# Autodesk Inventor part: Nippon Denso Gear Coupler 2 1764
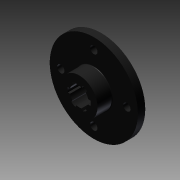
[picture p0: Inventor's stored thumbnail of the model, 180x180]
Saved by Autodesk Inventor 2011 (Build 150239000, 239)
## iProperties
Shininess: 64.0
Length Units: 11272
Angle Units: 11279
Time Units: 11290
Mass Units: 11286
Length Display Precision: 3
Angle Display Precision: 2
Category: FIRST Robotics Components
Manager: Ed Sparks
Company: FIRST CAD Library
Created: 2003-01
Part Number: Nippon Denso Gear Coupler 2 1764
Project: FIRST
Material: ABS Plastic
Document SubType Name: Modeling
Designer: Administrator
Engineer: Ed Sparks
Density: 1 g/cm^3
Density: 0.0
Volumn: 0.0
Area: 0.0
PropertySet Name: Model Information
Control State: 0
Master: False
Checked Out: False
Subject: Robot Component
Author: Administrator
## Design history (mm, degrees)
sketch "Sketch1"
  geometry: C1 r 38.1 at (0, 0)
  constraints: 1 centre point
  dimensions: "d2" = 76.2 diameter of C1
extrude "Extrusion1" new body sketch "Sketch1" stored distance "d0" = 6.35; taper "d1" = 0 deg
sketch "Sketch2"
  geometry: C1 r 38.1 at (0, 0) reference; 1 further point
  dimensions: "d3" = 0 horizontal distance of C1.centre point (0, 28.575); "d4" = 28.575 distance of C1.centre point (0, 28.575)
hole "Mounting Hole" sketch "Sketch2" at (0, 28.575) diameter "d5" = 6.35; stored, may be unused: countersink angle "d9" = 82 deg, drill point angle "d11" = 118 deg; dims "d6" = 12.7, "d7" = 9.525, "d8" = 6.35, "d10" = 19.05
pattern_circular "Circular Pattern1" dims angle "d14" = 360 deg
sketch "Sketch3"
  geometry: C1 r 38.1 at (0, 0) reference; C2 r 15.875 at (0, 0)
  constraints: 1 centre point, 1 coincident
  dimensions: "d15" = 31.75 diameter of C2
extrude "Extrusion2" join sketch "Sketch3" distance "d17" = 12.7; taper "d18" = 0 deg
sketch "Sketch8"
  geometry: C1 r 15.875 at (0, 0) reference; 1 further point
  constraints: 1 coincident
hole "Hole3" sketch "Sketch8" at (0, 0) diameter "d49" = 16.2; stored, may be unused: countersink angle "d53" = 82 deg, drill point angle "d55" = 0 deg; dims "d50" = 12.7, "d51" = 9.525, "d52" = 6.35, "d54" = 14.986
sketch "Sketch4"
  geometry: L1 (0, 0)-(-5, 8.66); L2 (0, 0)-(-10.16, 0); L3 (-2.058, 7.834)-(-3.036, 9.528); L4 (-5.556, 5.894)-(-6.528, 7.576); C1 r 15.875 at (0, 0) reference; A1 r 10 centre (0, 0) between (-3.036, 9.528) and (-6.528, 7.576); A2 r 8.1 centre (0, 0) between (-2.058, 7.834) and (-5.556, 5.894); A3 r 8.1 centre (0, 0) between (-5.556, 5.894) and (-2.058, 7.834) reference; 1 further point
  constraints: 9 end point, 7 point on circle, 2 centre point, 2 parallel, 1 coincident, 1 concentric, 1 horizontal
  dimensions: "d46" = 60 deg angle of L2 L1; "d47" = 4 distance between parallel lines of L3 L4; "d48" = 20 diameter of A1
extrude "Extrusion3" cut sketch "Sketch4" stored distance "d22" = 12.7; taper "d23" = 0 deg
pattern_circular "Circular Pattern2" dims angle "d26" = 360 deg
fillet "Fillet1" dims "d43" = 0.508
body "Solid1"
